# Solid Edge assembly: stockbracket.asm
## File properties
Author: Sham
Template: Iso Assembly.asm
Last saved by: Cadcim
Revision: 4
Application: Solid Edge
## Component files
Stock_support_base.par
thrust_bearing.par
adjusting_screw_nut.par
support_adjusting_screw.par
support_roller_bracket.par
stock_support_roller.par
adjusting_nut_handle.par
adjusting_screw_guide.par
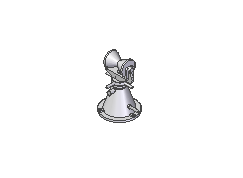
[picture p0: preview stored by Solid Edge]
